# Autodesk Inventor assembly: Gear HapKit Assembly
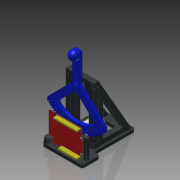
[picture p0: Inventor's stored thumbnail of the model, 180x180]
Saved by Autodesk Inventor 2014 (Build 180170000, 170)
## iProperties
Created: 2015-07
Part Number: Gear HapKit Assembly
Document SubType Name: Assembly
Designer: Brad Factor
Author: Brad Factor
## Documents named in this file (17)
- D:\Projects\Graduate School\Courses\Haptics\HapKit\Gear HapKit Assembly.iam
- D:\Projects\Graduate School\Courses\Haptics\HapKit\Sector Gear.ipt
- D:\Projects\Graduate School\Courses\Haptics\HapKit\5906K531.ipt
- D:\Projects\Graduate School\Courses\Haptics\HapKit\60355K702.ipt
- D:\Projects\Graduate School\Courses\Haptics\HapKit\98381A539.ipt
- D:\Projects\Graduate School\Courses\Haptics\HapKit\Drive Gear.ipt
- D:\Projects\Graduate School\Courses\Haptics\HapKit\Mabuchi Motor.ipt
- D:\Projects\Graduate School\Courses\Haptics\HapKit\92949A108.ipt
- D:\Projects\Graduate School\Courses\Haptics\HapKit\Front Plate.ipt
- D:\Projects\Graduate School\Courses\Haptics\HapKit\Side Plate.ipt
- D:\Projects\Graduate School\Courses\Haptics\HapKit\Side Plate Mirror.ipt
- D:\Projects\Graduate School\Courses\Haptics\HapKit\HapKit Board.ipt
- D:\Projects\Graduate School\Courses\Haptics\HapKit\Board Screw Support.ipt
- D:\Projects\Graduate School\Courses\Haptics\HapKit\Base Plate.ipt
- D:\Projects\Graduate School\Courses\Haptics\HapKit\90480A005.ipt
- D:\Projects\Graduate School\Courses\Haptics\HapKit\57295K73.ipt
- D:\Projects\Graduate School\Courses\Haptics\HapKit\Board Inlet Support.ipt
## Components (20 placed, 16 different names)
1. Sector Gear:1 — Mate:1, Mate:4, Mate:5, Mate:9, Flush:1, Rotation:1
2. 5906K531:1 — Mate:1, Mate:4, Mate:8
3. 60355K702:2 — Mate:5, Mate:8, Mate:16, Mate:39
4. 98381A539:1 — Mate:9, Flush:1
5. Drive Gear:1 — Mate:10, Mate:11, Mate:19, Rotation:1, Mate:27, Mate:44, Mate:45
6. Mabuchi Motor:1 — Mate:10, Mate:11, Mate:14, Mate:15, Mate:18, Mate:19, Flush:6, Mate:26
7. 92949A108:1 — Mate:14, Mate:20, Mate:22
8. 92949A108:2 — Mate:15, Mate:21, Mate:23
9. Front Plate:1 — Mate:16, Mate:18, Mate:20, Mate:21, Mate:22, Mate:23, Mate:24, Flush:2, Flush:3, Flush:4, Flush:5, Mate:25, Mate:39
10. Side Plate:1 — Mate:24, Flush:2, Flush:3
11. Side Plate Mirror:1 — Flush:4, Flush:5, Mate:25, Mate:32, Mate:33, Mate:34
12. HapKit Board:1 — Flush:6, Mate:26, Mate:27, Mate:28, Mate:29, Mate:30, Mate:31, Flush:7, Mate:35, Mate:36, Mate:37, Mate:38
13. Board Screw Support:1 — Mate:28, Mate:29, Mate:42, Mate:43, Angle:1, Angle:2
14. Board Inlet Support:1 — Mate:30, Mate:31, Flush:7
15. Base Plate:1 — Mate:32, Mate:33, Mate:34
16. 92949A108:3 — Mate:35, Mate:37, Mate:40
17. 92949A108:4 — Mate:36, Mate:38, Mate:41
18. 90480A005:1 — Mate:40, Mate:42, Angle:1
19. 90480A005:2 — Mate:41, Mate:43, Angle:2
20. 57295K73:1 — Mate:44, Mate:45
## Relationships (48: Mate 38, Flush 7, Angle 2, RelateRotation 1)
- Mate:1: Sector Gear:1 ↔ 5906K531:1
- Mate:4: Sector Gear:1 ↔ 5906K531:1
- Mate:5: Sector Gear:1 ↔ 60355K702:2
- Mate:8: 5906K531:1 ↔ 60355K702:2
- Mate:9: Sector Gear:1 ↔ 98381A539:1
- Flush:1: Sector Gear:1 ↔ 98381A539:1
- Mate:10: Drive Gear:1 ↔ Mabuchi Motor:1
- Mate:11: Drive Gear:1 ↔ Mabuchi Motor:1
- Mate:14: Mabuchi Motor:1 ↔ 92949A108:1
- Mate:15: Mabuchi Motor:1 ↔ 92949A108:2
- Mate:16: 60355K702:2 ↔ Front Plate:1
- Mate:18: Mabuchi Motor:1 ↔ Front Plate:1
- Mate:19: Drive Gear:1 ↔ Mabuchi Motor:1
- Mate:20: 92949A108:1 ↔ Front Plate:1
- Mate:21: 92949A108:2 ↔ Front Plate:1
- Mate:22: 92949A108:1 ↔ Front Plate:1
- Mate:23: 92949A108:2 ↔ Front Plate:1
- Rotation:1 [RelateRotation]: Sector Gear:1 ↔ Drive Gear:1
- Mate:24: Front Plate:1 ↔ Side Plate:1
- Flush:2: Front Plate:1 ↔ Side Plate:1
- Flush:3: Front Plate:1 ↔ Side Plate:1
- Flush:4: Front Plate:1 ↔ Side Plate Mirror:1
- Flush:5: Front Plate:1 ↔ Side Plate Mirror:1
- Mate:25: Front Plate:1 ↔ Side Plate Mirror:1
- Flush:6: Mabuchi Motor:1 ↔ HapKit Board:1
- Mate:26: Mabuchi Motor:1 ↔ HapKit Board:1
- Mate:27: Drive Gear:1 ↔ HapKit Board:1
- Mate:28: HapKit Board:1 ↔ Board Screw Support:1
- Mate:29: HapKit Board:1 ↔ Board Screw Support:1
- Mate:30: HapKit Board:1 ↔ Board Inlet Support:1
- Mate:31: HapKit Board:1 ↔ Board Inlet Support:1
- Flush:7: HapKit Board:1 ↔ Board Inlet Support:1
- Mate:32: Side Plate Mirror:1 ↔ Base Plate:1
- Mate:33: Side Plate Mirror:1 ↔ Base Plate:1
- Mate:34: Side Plate Mirror:1 ↔ Base Plate:1
- Mate:35: HapKit Board:1 ↔ 92949A108:3
- Mate:36: HapKit Board:1 ↔ 92949A108:4
- Mate:37: HapKit Board:1 ↔ 92949A108:3
- Mate:38: HapKit Board:1 ↔ 92949A108:4
- Mate:39: 60355K702:2 ↔ Front Plate:1
- Mate:40: 92949A108:3 ↔ 90480A005:1
- Mate:41: 92949A108:4 ↔ 90480A005:2
- Mate:42: Board Screw Support:1 ↔ 90480A005:1
- Mate:43: Board Screw Support:1 ↔ 90480A005:2
- Angle:1: Board Screw Support:1 ↔ 90480A005:1
- Angle:2: Board Screw Support:1 ↔ 90480A005:2
- Mate:44: Drive Gear:1 ↔ 57295K73:1
- Mate:45: Drive Gear:1 ↔ 57295K73:1
